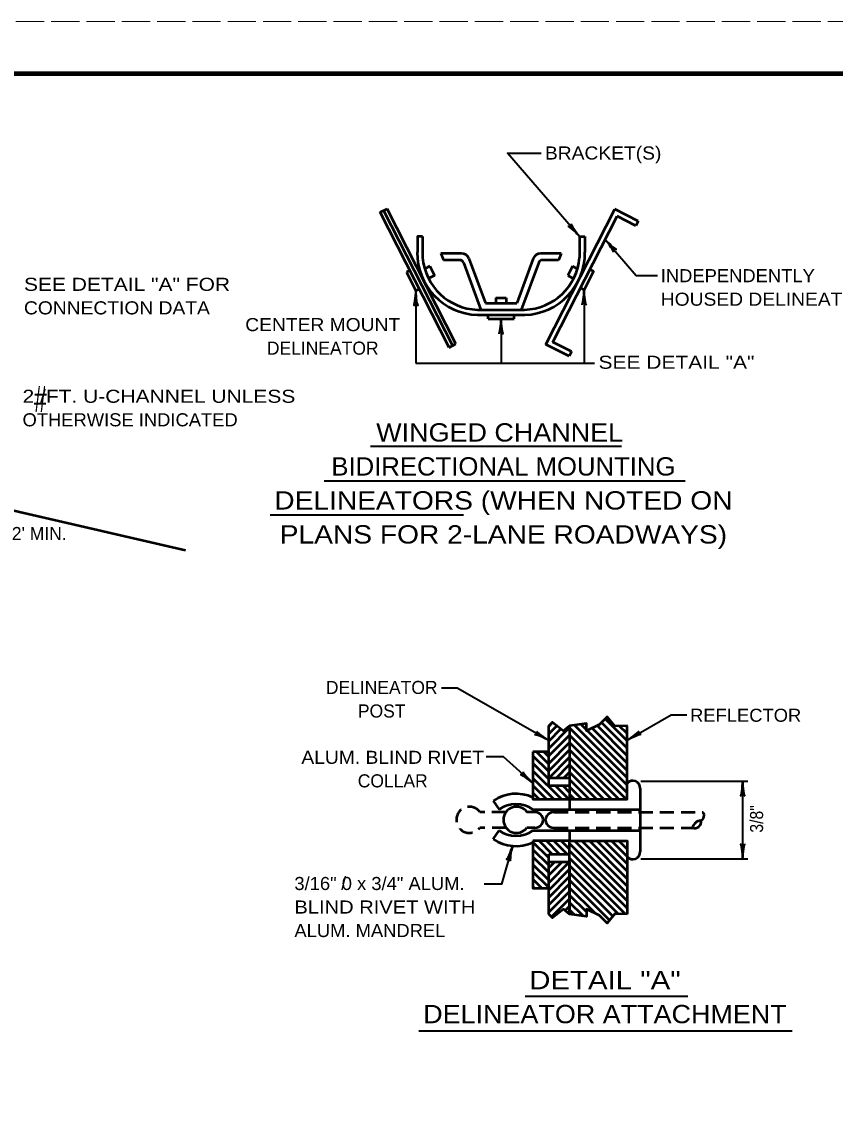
# Model space of a CAD drawing. Extents: x -54 to 626, y -41 to 399.
# Drawn here: x 176.2 to 331.9, y 192.5 to 398.7 of the extents above; entities that cross this region are included whole.
import ezdxf
from ezdxf.enums import TextEntityAlignment as Align

# ---------------------------------------------------------------- set-up
doc = ezdxf.new("R2010")
doc.units = 0
doc.header["$LTSCALE"] = 0.9
doc.linetypes.add('LONG_DASHED', pattern=[7.5, 6, -1.5])
doc.linetypes.add('MEDIUM_DASHED', pattern=[4.5, 3, -1.5])
doc.layers.add('1', color=7, linetype='Continuous', lineweight=35)
doc.layers.add('61', color=7, linetype='Continuous', lineweight=35)

msp = doc.modelspace()

# ---------------------------------------------------------------- linework, layer by layer
at = {"layer": '1', "lineweight": 53}
for p, q in [((244.8049, 362.221), (246.1415, 362.902)), ((259.3072, 337.0627), (246.1415, 362.902)), ((257.9706, 336.3818), (244.8049, 362.221)), ((245.4732, 362.5615), (258.6385, 336.7221)), ((276.502, 336.9634), (289.6677, 362.8027)), ((277.8469, 337.4004), (290.1047, 361.4576)), ((294.1227, 360.5327), (289.6677, 362.8027)), ((293.6687, 359.6417), (290.1047, 361.4576)), ((294.1227, 360.5327), (293.6687, 359.6417)), ((252.9274, 357.5884), (252.9274, 353.5884)), ((282.9274, 357.5884), (283.9274, 357.5884)), ((282.9274, 357.5884), (282.9274, 353.5884)), ((283.9274, 357.5884), (283.9274, 354.5884)), ((260.3815, 354.3384), (256.4274, 354.3384)), ((256.4274, 354.3384), (256.9274, 353.0884)), ((260.0327, 353.0884), (256.9274, 353.0884)), ((260.7365, 352.5977), (264.0557, 343.5884)), ((261.789, 353.357), (264.9274, 344.8384)), ((274.0658, 353.3569), (270.9274, 344.8384)), ((275.1182, 352.5977), (271.799, 343.5884)), ((279.4274, 354.3384), (275.4733, 354.3384)), ((278.9274, 353.0884), (275.8219, 353.0884)), ((279.4274, 354.3384), (278.9274, 353.0884)), ((250.4797, 351.0834), (249.8113, 350.7429)), ((249.8113, 350.7429), (251.6273, 347.1787)), ((254.2748, 351.8947), (253.3309, 351.4138)), ((254.2748, 351.8947), (255.1827, 350.1127)), ((281.58, 351.8947), (280.6721, 350.1127)), ((281.58, 351.8947), (282.5239, 351.4138)), ((285.6167, 350.9613), (283.8008, 347.3972)), ((284.9338, 351.3092), (285.6167, 350.9613)), ((255.1827, 350.1127), (254.0712, 349.5462)), ((280.6721, 350.1127), (281.7836, 349.5462)), ((252.2957, 347.5194), (251.6273, 347.1787)), ((283.1178, 347.7452), (283.8008, 347.3972)), ((264.9274, 344.8384), (270.9274, 344.8384)), ((266.9274, 345.8384), (268.9274, 345.8384)), ((266.9274, 345.8384), (266.9274, 344.8384)), ((268.9274, 345.8384), (268.9274, 344.8384)), ((263.4274, 343.5884), (272.4274, 343.5884)), ((263.4274, 342.5884), (272.4274, 342.5884)), ((265.4274, 341.8384), (265.4274, 342.5884)), ((270.4274, 341.8384), (270.4274, 342.5884)), ((265.4274, 341.8384), (270.4274, 341.8384)), ((257.9702, 336.3816), (259.3072, 337.0627)), ((280.957, 334.6935), (276.502, 336.9634)), ((281.411, 335.5845), (277.8469, 337.4004)), ((281.411, 335.5845), (280.957, 334.6935)), ((277.0297, 263.8971), (277.7804, 264.6477)), ((277.0297, 262.4828), (278.5723, 264.0254)), ((292.0297, 254.0429), (281.9531, 264.1196)), ((284.2351, 263.2518), (283.1955, 264.2914)), ((292.0297, 258.2856), (286.2738, 264.0415)), ((292.0297, 259.6998), (287.1041, 264.6255)), ((292.0297, 261.114), (287.8111, 265.3327)), ((292.0297, 262.5283), (290.5928, 263.9652)), ((292.0297, 263.9424), (291.9812, 263.991)), ((277.0297, 259.6544), (281.0297, 263.6544)), ((277.0297, 261.0687), (279.3741, 263.413)), ((277.0297, 258.2403), (281.0297, 262.2403)), ((292.0297, 252.6287), (281.0297, 263.6287)), ((292.0297, 251.2145), (281.0297, 262.2145)), ((292.0297, 255.4572), (284.3679, 263.119)), ((292.0297, 256.8714), (285.3208, 263.5802)), ((277.0297, 256.826), (281.0297, 260.826)), ((291.8382, 249.9919), (281.0297, 260.8003)), ((277.0297, 259.0019), (274.0297, 259.0019)), ((277.0297, 255.2448), (274.0297, 258.2448)), ((277.0297, 256.659), (274.6868, 259.0019)), ((277.0297, 258.0732), (276.1011, 259.0019)), ((277.0297, 255.4117), (281.0297, 259.4117)), ((277.0341, 254.0019), (281.0297, 257.9976)), ((290.4239, 249.9919), (281.0297, 259.3861)), ((289.0097, 249.9919), (281.0297, 257.9719)), ((277.0297, 253.8306), (274.0297, 256.8306)), ((278.4483, 254.0019), (281.0297, 256.5833)), ((287.5955, 249.9919), (281.0297, 256.5577)), ((279.4542, 249.9919), (274.0297, 255.4163)), ((278.04, 249.9919), (274.0297, 254.0022)), ((277.0297, 252.5019), (277.0297, 254.0019)), ((279.8625, 254.0019), (281.0297, 255.1692)), ((286.1812, 249.9919), (281.0297, 255.1434)), ((284.7671, 249.9919), (281.0297, 253.7292)), ((276.6257, 249.9919), (274.0297, 252.5879)), ((281.0297, 252.5019), (277.0297, 252.5019)), ((280.8684, 249.9919), (278.3584, 252.5019)), ((281.0297, 251.2448), (279.7727, 252.5019)), ((283.3528, 249.9919), (281.0297, 252.315)), ((294.5297, 251.9919), (294.5297, 239.9919)), ((266.4054, 249.646), (267.5297, 247.9919)), ((275.2116, 249.9919), (274.0297, 251.1737)), ((281.9387, 249.9919), (281.0297, 250.9008)), ((281.0297, 249.9919), (281.0297, 247.9919)), ((274.3558, 247.4919), (272.8558, 247.4919)), ((274.0297, 247.9919), (294.5297, 247.9919)), ((266.4054, 242.3378), (267.5297, 243.9919)), ((274.3558, 244.4919), (272.8558, 244.4919)), ((274.0297, 243.9919), (294.5297, 243.9919)), ((281.0297, 243.9919), (281.0297, 241.9919)), ((281.0297, 241.9919), (274.0297, 241.9919)), ((277.0297, 238.7481), (274.0297, 241.7481)), ((277.7101, 239.4819), (275.2001, 241.9919)), ((279.1243, 239.4819), (276.6143, 241.9919)), ((280.5386, 239.4819), (278.0286, 241.9919)), ((281.0297, 240.4049), (279.4427, 241.9919)), ((281.0297, 241.8192), (280.857, 241.9919)), ((292.0297, 230.5231), (281.0297, 241.5231)), ((292.0297, 231.9373), (281.9751, 241.9919)), ((292.0297, 233.3515), (283.3893, 241.9919)), ((292.0297, 234.7657), (284.8036, 241.9919)), ((292.0297, 236.1799), (286.2177, 241.9919)), ((292.0297, 237.5942), (287.632, 241.9919)), ((292.0297, 239.0083), (289.0462, 241.9919)), ((292.0297, 240.4226), (290.4604, 241.9919)), ((292.0297, 241.8367), (291.8746, 241.9919)), ((277.0297, 237.3338), (274.0297, 240.3338)), ((277.0297, 239.4819), (281.0297, 239.4819)), ((277.0297, 237.9819), (277.0297, 239.4819)), ((292.0297, 229.1088), (281.0297, 240.1088)), ((277.0297, 235.9197), (274.0297, 238.9197)), ((277.0297, 234.5054), (274.0297, 237.5054)), ((277.0297, 236.8233), (278.1883, 237.9819)), ((277.0297, 235.4092), (279.6025, 237.9819)), ((277.0297, 233.9949), (281.0168, 237.9819)), ((291.7268, 227.9976), (281.0297, 238.6947)), ((290.2858, 228.0244), (281.0297, 237.2804)), ((277.0297, 233.0913), (274.0297, 236.0913)), ((277.0297, 232.5807), (281.0297, 236.5807)), ((277.0297, 231.1665), (281.0297, 235.1665)), ((289.3077, 227.5882), (281.0297, 235.8662)), ((275.7248, 232.9819), (274.0297, 234.677)), ((274.3106, 232.9819), (274.0297, 233.2627)), ((277.0297, 229.7523), (281.0297, 233.7523)), ((288.6714, 226.8103), (281.0297, 234.452)), ((285.9859, 228.0817), (281.0297, 233.0377)), ((277.0297, 228.3381), (281.0297, 232.3381)), ((277.5731, 227.4672), (281.0297, 230.9238)), ((284.2351, 228.4183), (281.0297, 231.6236)), ((280.1844, 228.6643), (281.0297, 229.5097)), ((283.6031, 227.6361), (281.0297, 230.2093)), ((280.9721, 228.0377), (281.0297, 228.0954)), ((281.9619, 227.863), (281.0297, 228.7952))]:
    msp.add_line(p, q, dxfattribs=at)
at = {"layer": '1'}
for p, q in [((251.6273, 347.1787), (251.6273, 333.3384)), ((283.8008, 347.3972), (283.8008, 333.3384)), ((267.9274, 341.8384), (267.9274, 333.3384)), ((251.6273, 333.3384), (285.8008, 333.3384)), ((294.6437, 253.4017), (315.1074, 253.4017)), ((314.1074, 253.4017), (314.1074, 238.5822)), ((294.6437, 238.5822), (315.1074, 238.5822))]:
    msp.add_line(p, q, dxfattribs=at)
at = {"layer": '1', "lineweight": 40}
for p, q in [((242.9665, 317.5184), (290.9377, 317.5184)), ((234.0748, 310.8475), (303.1444, 310.8475)), ((223.7541, 304.3353), (260.75, 304.3353)), ((272.5222, 212.3217), (303.6616, 212.3217)), ((252.2317, 205.69), (323.554, 205.69))]:
    msp.add_line(p, q, dxfattribs=at)
at = {"layer": '1', "linetype": 'MEDIUM_DASHED', "lineweight": 53}
for p, q in [((268.8532, 247.4919), (263.8558, 247.4919)), ((278.0297, 247.4919), (306.5297, 247.4919)), ((268.8946, 244.4919), (263.8558, 244.4919)), ((278.0297, 244.4919), (304.5297, 244.4919))]:
    msp.add_line(p, q, dxfattribs=at)
at = {"layer": '1'}
for points in [[(282.9274, 357.5884), (269.1462, 373.5101), (275.5963, 373.5101)], [(287.855, 357.0423), (293.7763, 350.1585), (297.8252, 350.1585)], [(277.0297, 261.1905), (259.5427, 271.2168), (256.5292, 271.2168)], [(292.0297, 261.2528), (300.4466, 266.0787), (303.46, 266.0787)], [(274.0297, 253.0153), (268.4038, 258.0402), (265.089, 258.0402)], [(270.1342, 241.0187), (268.002, 233.724), (264.6873, 233.724)]]:
    msp.add_lwpolyline(points, dxfattribs=at)
at = {"layer": '1', "lineweight": 53}
for points in [[(252.9274, 357.5884), (251.9274, 357.5884), (251.9274, 354.5884)], [(163.6023, 307.7896), (175.8538, 304.9611), (207.6092, 297.6296)], [(277.0297, 263.9919), (277.741, 264.6787), (278.8775, 263.7856), (279.8516, 263.0548), (281.0297, 263.9919)], [(281.0297, 263.9919), (281.0297, 254.0019), (277.0297, 254.0019), (277.0297, 259.0019), (277.0297, 263.9919)], [(292.0297, 263.9919), (289.6738, 263.948), (288.2127, 265.7344), (286.7515, 264.2727), (284.2351, 263.0548), (284.2351, 264.4352), (281.0297, 263.9919), (281.0297, 254.0019), (281.0297, 252.5019), (281.0297, 249.9919)], [(281.0297, 249.9919), (292.0297, 249.9919), (292.0297, 263.9919)], [(274.0297, 259.0019), (274.0297, 249.9919), (281.0297, 249.9919)], [(274.0297, 241.9919), (274.0297, 232.9819), (277.0297, 232.9819)], [(281.0297, 241.9919), (292.0297, 241.9919), (292.0297, 227.9919)], [(292.0297, 227.9919), (289.6738, 228.0358), (288.2127, 226.2494), (286.7515, 227.7111), (284.2351, 228.9291), (284.2351, 227.5487), (281.0297, 227.9919), (281.0297, 237.9819), (281.0297, 239.4819), (281.0297, 241.9919)], [(277.0297, 227.9919), (277.0297, 232.9819), (277.0297, 237.9819), (281.0297, 237.9819), (281.0297, 227.9919)], [(281.0297, 227.9919), (279.8516, 228.9291), (278.8775, 228.1983), (277.741, 227.3051), (277.0297, 227.9919)]]:
    msp.add_lwpolyline(points, dxfattribs=at)
for centre, radius, start, end in [((263.7871, 354.4786), 11.8961, 179.46942, 268.10829), ((263.7871, 354.4786), 10.8961, 184.68607, 268.10829), ((260.0328, 352.3384), 0.75, 20.22252, 90), ((260.3815, 352.8384), 1.5, 20.22523, 90), ((272.0677, 354.4786), 10.8961, 271.89171, 355.31393), ((272.0677, 354.4786), 11.8961, 271.89171, 0.53058), ((275.4734, 352.8384), 1.5, 90, 159.77596), ((275.822, 352.3384), 0.75, 90, 159.77389), ((293.1182, 252.0881), 1.4148, 356.1022, 140.29498), ((270.7797, 243.2107), 7.7812, 65.31239, 124.20546), ((270.7797, 243.2107), 5.7812, 55.79454, 124.20546), ((270.8736, 246.0195), 2.5, 36.08371, 322.33574), ((274.4404, 245.9919), 1.5024, 266.7708, 93.22921), ((277.9451, 245.9919), 1.5024, 86.77079, 273.2292), ((305.7057, 246.8395), 1.0511, 294.14682, 38.36982), ((304.9527, 245.6256), 1.2101, 249.5389, 12.15549), ((306.2385, 244.1386), 1.7449, 93.37761, 168.31678), ((270.7797, 248.7732), 5.7812, 235.79454, 304.20546), ((270.7797, 248.7732), 7.7812, 235.79454, 294.68761), ((293.1182, 239.8957), 1.4148, 219.70502, 3.8978)]:
    msp.add_arc(centre, radius, start, end, dxfattribs=at)
at = {"layer": '1', "linetype": 'MEDIUM_DASHED', "lineweight": 53}
msp.add_arc((261.8736, 246.0195), 2.5, 36.08371, 322.33574, dxfattribs=at)
at = {"layer": '1', "lineweight": 40}
for centre, major_axis, ratio, start_param, end_param in [((282.0044, 358.2326), (1.2867, -1.248), 0.122415, 0.89635335, 3.14159265), ((282.3541, 358.5741), (-1.0167, 1.443), 0.07063, 6.28230741, 8.55970261), ((288.4253, 356.0549), (1.0122, -1.4461), 0.07063, 6.28230741, 8.55970261), ((288.7761, 356.3953), (-1.2829, 1.2519), 0.122415, 0.89635335, 3.14159265), ((251.4156, 346.0582), (0.1757, 1.7565), 0.07063, 3.14071475, 5.41810995), ((251.4156, 346.0582), (0.1757, 1.7565), 0.07063, 3.14071475, 5.41810995), ((251.9035, 346.0876), (-0.1562, 1.7857), 0.122415, 0.89635335, 3.14159265), ((251.9035, 346.0876), (-0.1562, 1.7857), 0.122415, 0.89635335, 3.14159265), ((283.5892, 346.2767), (0.1757, 1.7565), 0.07063, 3.14071475, 5.41810995), ((284.0771, 346.306), (-0.1562, 1.7857), 0.122415, 0.89635335, 3.14159265), ((267.7158, 340.7179), (0.1757, 1.7565), 0.07063, 3.14071475, 5.41810995), ((268.2037, 340.7472), (-0.1562, 1.7857), 0.122415, 0.89635335, 3.14159265), ((275.9457, 261.4936), (1.6268, -0.7527), 0.122415, 0.89635335, 3.14159265), ((275.9457, 261.4936), (1.6268, -0.7527), 0.122415, 0.89635335, 3.14159265), ((276.1629, 261.9314), (-1.4364, 1.026), 0.07063, 6.28230741, 8.55970261), ((276.1629, 261.9314), (-1.4364, 1.026), 0.07063, 6.28230741, 8.55970261), ((292.839, 262.0353), (-1.4715, -1.0237), 0.122415, 0.89635335, 3.14159265), ((292.839, 262.0353), (-1.4715, -1.0237), 0.122415, 0.89635335, 3.14159265), ((293.1071, 261.6266), (-1.6111, -0.7213), 0.07063, 3.14071475, 5.41810995), ((293.1071, 261.6266), (-1.6111, -0.7213), 0.07063, 3.14071475, 5.41810995), ((273.0318, 253.5361), (1.4358, -1.0731), 0.122415, 0.89635335, 3.14159265), ((273.0318, 253.5361), (1.4358, -1.0731), 0.122415, 0.89635335, 3.14159265), ((273.335, 253.9196), (1.193, -1.301), 0.07063, 3.14071475, 5.41810995), ((273.335, 253.9196), (1.193, -1.301), 0.07063, 3.14071475, 5.41810995), ((313.8958, 252.2812), (0.1757, 1.7565), 0.07063, 3.14071475, 5.41810995), ((313.8958, 252.2812), (0.1757, 1.7565), 0.07063, 3.14071475, 5.41810995), ((314.3837, 252.3105), (-0.1562, 1.7857), 0.122415, 0.89635335, 3.14159265), ((314.3837, 252.3105), (-0.1562, 1.7857), 0.122415, 0.89635335, 3.14159265), ((313.8311, 239.6734), (0.1562, -1.7857), 0.122415, 0.89635335, 3.14159265), ((314.319, 239.7027), (-0.1757, -1.7565), 0.07063, 3.14071475, 5.41810995), ((269.6167, 240.0026), (0.6614, 1.6366), 0.07063, 3.14071475, 5.41810995), ((269.6167, 240.0026), (0.6614, 1.6366), 0.07063, 3.14071475, 5.41810995), ((270.0932, 239.8939), (0.3511, 1.7578), 0.122415, 0.89635335, 3.14159265), ((270.0932, 239.8939), (0.3511, 1.7578), 0.122415, 0.89635335, 3.14159265)]:
    msp.add_ellipse(centre, major_axis=major_axis, ratio=ratio, start_param=start_param, end_param=end_param, dxfattribs=at)
at = {"layer": '61', "linetype": 'LONG_DASHED', "lineweight": 13}
msp.add_line((-54.3422, 398.7039), (625.6777, 398.7039), dxfattribs=at)
at = {"layer": '61', "lineweight": 158}
msp.add_lwpolyline([(614.6977, 388.7039), (-24.3422, 388.7039), (-24.3422, -31.3161)], dxfattribs=at)

# ---------------------------------------------------------------- texts
at = {"layer": '1'}
for s, height, width, p in [('BRACKET(S)', 2.5, 1.1, (276.3104, 372.3157)), ('INDEPENDENTLY', 2.5, 1.05, (298.4603, 348.8497)), ('SEE DETAIL "A" FOR', 2.5, 1.2, (176.6979, 347.1972)), ('HOUSED DELINEATOR', 2.5, 1.1, (298.4603, 344.3497)), ('CONNECTION DATA', 2.5, 1.1, (176.6979, 342.6972)), ('SEE DETAIL "A"', 2.5, 1.2, (286.5518, 332.2899)), ('2 /FT. U-CHANNEL UNLESS', 2.5, 1.2, (176.4235, 325.7826)), ('#', 5, 0.65, (178.625, 324.0068)), ('OTHERWISE INDICATED', 2.5, 1.05, (176.4235, 321.2826)), ('REFLECTOR', 2.5, 1.05, (304.0627, 264.7723)), ('3/16" 0 x 3/4" ALUM.', 2.5, 1.05, (228.4096, 232.5948)), ('BLIND RIVET WITH', 2.5, 1.15, (228.4096, 228.0948)), ('ALUM. MANDREL', 2.5, 1.05, (228.4096, 223.5948))]:
    msp.add_text(s, height=height, dxfattribs=dict(at, width=width)).set_placement(p)
for s, height, width, p in [('CENTER MOUNT', 2.5, 1.1, (233.8216, 339.4908)), ('WINGED CHANNEL ', 3.5, 1.1, (268.3715, 318.371)), ('BIDIRECTIONAL MOUNTING', 3.5, 1.05, (268.3715, 311.871)), ('DELINEATORS (WHEN NOTED ON', 3.5, 1.15, (268.3715, 305.371)), ('PLANS FOR 2-LANE ROADWAYS)', 3.5, 1.15, (268.3715, 298.871)), ('ALUM. BLIND RIVET', 2.5, 1.1, (247.2093, 256.7291)), ('DETAIL "A"', 3.5, 1.2, (287.7901, 213.6207)), ('DELINEATOR ATTACHMENT', 3.5, 1.1, (287.7901, 207.1207))]:
    msp.add_text(s, height=height, dxfattribs=dict(at, width=width)).set_placement(p, align=Align.CENTER)
for s, p in [('DELINEATOR', (233.8216, 334.9908)), ('DELINEATOR', (245.1, 270.093)), ('POST', (245.1, 265.593)), ('COLLAR', (247.2094, 252.2291))]:
    msp.add_text(s, height=2.5, dxfattribs=at).set_placement(p, align=Align.CENTER)
for s, p in [("2' MIN.", (174.3769, 299.531)), ('/', (237.3715, 232.6421))]:
    msp.add_text(s, height=2.5, dxfattribs=at).set_placement(p)
at = {"layer": '1', "width": 0.9}
msp.add_text('3/8"', height=2.5, rotation=90, dxfattribs=at).set_placement((318.0249, 243.571))

doc.saveas('drawing.dxf')
